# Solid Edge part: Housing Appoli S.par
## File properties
Title: Housing Appoli S
Author: petr.kostka
Keywords: ---
Template: Part Robe 03_24.par
Last saved by: petr.kostka
Revision: 44
Application: Solid Edge
Company: 19030927-01M
Hustota: 2680,000 kg/m^3
Přesnost: 0,990
Username: petr.kostka
Typ obsahu dokumentu: 0
Material: LM6 - slitina hliníku
Face Style: Model Default
Fill Style: Normal
Virtual Style: Normal
Skupiny: Slitiny hliníku
LibraryName: Robe knihovna - Konstrukce
Coef. of Thermal Exp: 0.0
Thermal Conductivity: 0.0
Specific Heat: 0.0
Modulus of Elasticity: 0.0
Poisson's Ratio: 0.0
Yield Stress: 0.0
Ultimate Stress: 0.0
Elongation: 0.0
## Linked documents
19030927-01M Housing Appoli S.par
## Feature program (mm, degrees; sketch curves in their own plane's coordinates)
part copy "KopírovanáSoučást_2"
sketch used by "Vysunutí_1" plane through (0, -6.3, 0) normal (0, -1, 0) x-axis (0, 0, 1)
extrude "Vysunutí_1" add finite 51 along -normal
sketch for "Vysunutí_2" #1 plane through (43, 73, 0) normal (0, 1, 0) x-axis (0, 0, 1)
sketch for "Vysunutí_2" #2 plane through (43, 73, 0) normal (0, 1, 0) x-axis (0, 0, 1)
sketch for "Vysunutí_2" #3 plane through (43, 73, 0) normal (0, 1, 0) x-axis (0, 0, 1)
  circle centre (-43.87, -11) radius 6.0255
sketch for "Vysunutí_2" #4 plane through (43, 73, 0) normal (0, 1, 0) x-axis (0, 0, 1)
  circle centre (43.87, -11) radius 6.0255
sketch for "Vysunutí_2" #5 plane through (43, 73, 0) normal (0, 1, 0) x-axis (0, 0, 1)
  circle centre (43.87, -75) radius 6.0255
extrude "Vysunutí_2" add finite 35 along -normal
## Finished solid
Body 1: solid body, 810 faces, 1738 edges, 946 vertices.
  Faces by surface: blend 242, cylinder 223, plane 138, sphere 104, torus 53, swept 28, cone 18, spline 4
  Edges by curve: circle 664, line 482, intersection 346, ellipse 178, spline 64, curve on surface 4
Bounding box of the edges (mm; curved faces can reach further): 124.156 x 79.300 x 132.000, from (-62.0783, -6.3, -66) to (62.0783, 73, 66).
Cylindrical faces by radius (mm): R0.2 x2, R0.5 x102, R0.7128 x1, R0.9249 x1, R0.9359 x1, R1 x54, R1.8 x4, R2.0009 x2, R2.067 x1, R2.52 x1, R3.3235 x2, R6.9 x2, R17.885 x2, R391.3015 x48
Conical faces (half-angle, radius in mm at the cone's reference point): 1.5 deg R11.25 x1, 2 deg R13.6516 x4, 3 deg R6.5 x4, 5 deg R6.5 x1, 5 deg R25.015 x2, 8 deg R26.25 x2, 45 deg R3.6235 x2, 45 deg R7.4 x2
Toroidal faces (ring radius, tube radius in mm): R0.5 r0.3 x2, R2.22 r0.3 x1, R2.82 r0.3 x1, R6.0255 r0.5 x4, R6.2251 r0.3 x1, R6.6 r0.3 x2, R6.8624 r0.3 x1, R8.8116 r1 x16, R10.7629 r0.5 x1, R11.8129 r1 x4, R12.905 r1 x6, R14.1345 r0.5 x4, R17.585 r0.3 x2, R18.185 r0.3 x2, R24.7401 r0.3 x2, R25.3774 r0.3 x2, R25.8154 r0.5 x2
Spherical faces by radius (mm): R0.5 x60, R1 x44
Planar faces by outward normal: +x 3, +y 73, +z 15, -x 3, -y 1, -z 17, oblique 26
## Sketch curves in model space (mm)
arc centre (45.1095, -6.3, -45.1095) radius 15.1688 from (45.1095, -6.3, -60.2783) through (56.1429, -6.3, -55.5189) to (60.2783, -6.3, -45.1095)
line (60.2783, -6.3, -45.1095) -> (60.2783, -6.3, 45.1095)
arc centre (45.1095, -6.3, 45.1095) radius 15.1688 from (60.2783, -6.3, 45.1095) through (55.5189, -6.3, 56.1429) to (45.1095, -6.3, 60.2783)
line (45.1095, -6.3, 60.2783) -> (-45.1095, -6.3, 60.2783)
arc centre (-45.1095, -6.3, 45.1095) radius 15.1688 from (-45.1095, -6.3, 60.2783) through (-56.1429, -6.3, 55.5189) to (-60.2783, -6.3, 45.1095)
line (-60.2783, -6.3, 45.1095) -> (-60.2783, -6.3, -45.1095)
arc centre (-45.1095, -6.3, -45.1095) radius 15.1688 from (-60.2783, -6.3, -45.1095) through (-55.5189, -6.3, -56.1429) to (-45.1095, -6.3, -60.2783)
line (-45.1095, -6.3, -60.2783) -> (45.1095, -6.3, -60.2783)
circle centre (32, 73, 43.87) radius 6.0255
circle centre (-32, 73, 43.87) radius 6.0255
circle centre (-32, 73, -43.87) radius 6.0255
circle centre (32, 73, -43.87) radius 6.0255
circle centre (43, 73, 0) radius 10.7629
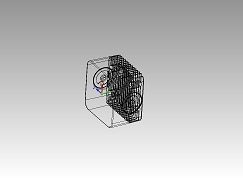
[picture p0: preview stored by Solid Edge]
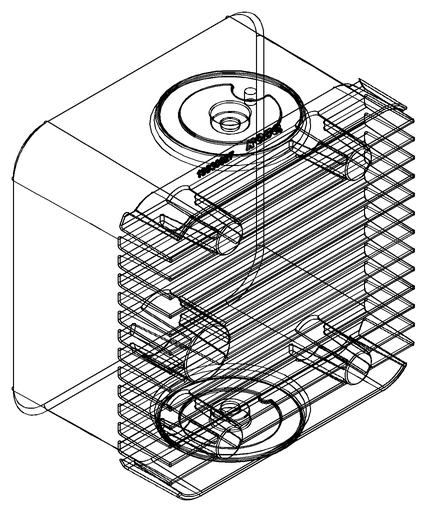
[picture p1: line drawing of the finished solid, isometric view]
